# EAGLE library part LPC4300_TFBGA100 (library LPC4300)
TFBGA100 - SOT926-1 TFBGA100: plastic thin fine-pitch ball grid array package; 100 balls body 9 x 9 x 0.7 mm; Solderland 0.40 mm diameter Grid 0.8 x 0.8 mm
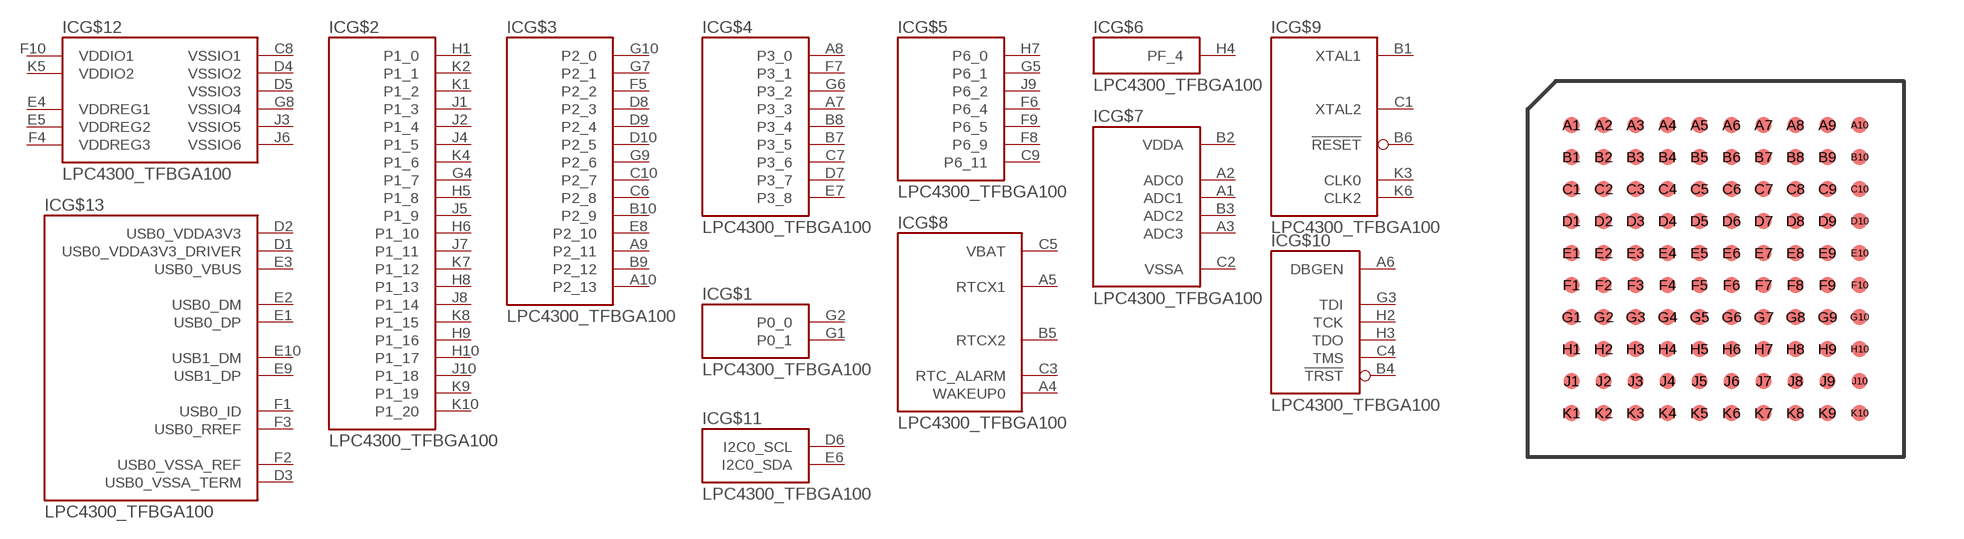
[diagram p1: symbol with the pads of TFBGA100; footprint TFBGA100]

Designator prefix IC; gates G$1=100_1_PORT0 G$2=100_2_PORT1 G$3=100_3_PORT2 G$4=100_4_PORT3 G$5=100_7_PORT6 G$6=100_16_PORTF G$7=100_17_ANA G$8=100_18_RTC G$9=100_19_CLK G$10=100_20_DBUG G$11=100_21_I2C G$12=100_22_SUP G$13=100_23_USB

## LPC4300_TFBGA100  [TFBGA100]
A1  G$7:ADC1  in
A2  G$7:ADC0  in
A3  G$7:ADC3  in
A4  G$8:WAKEUP0  in
A5  G$8:RTCX1  in
A6  G$10:DBGEN  in
A7  G$4:P3_3
A8  G$4:P3_0
A9  G$3:P2_11
A10  G$3:P2_13
B1  G$9:XTAL1  in
B2  G$7:VDDA  sup
B3  G$7:ADC2  in
B4  G$10:!TRST
B5  G$8:RTCX2  out
B6  G$9:!RESET  in
B7  G$4:P3_5
B8  G$4:P3_4
B9  G$3:P2_12
B10  G$3:P2_9
C1  G$9:XTAL2  out
C2  G$7:VSSA  sup
C3  G$8:RTC_ALARM  out
C4  G$10:TMS
C5  G$8:VBAT  pwr
C6  G$3:P2_8
C7  G$4:P3_6
C8  G$12:VSSIO1  sup
C9  G$5:P6_11
C10  G$3:P2_7
D1  G$13:USB0_VDDA3V3_DRIVER
D2  G$13:USB0_VDDA3V3
D3  G$13:USB0_VSSA_TERM
D4  G$12:VSSIO2  sup
D5  G$12:VSSIO3  sup
D6  G$11:I2C0_SCL
D7  G$4:P3_7
D8  G$3:P2_3
D9  G$3:P2_4
D10  G$3:P2_5
E1  G$13:USB0_DP
E2  G$13:USB0_DM
E3  G$13:USB0_VBUS
E4  G$12:VDDREG1  sup
E5  G$12:VDDREG2  sup
E6  G$11:I2C0_SDA
E7  G$4:P3_8
E8  G$3:P2_10
E9  G$13:USB1_DP
E10  G$13:USB1_DM
F1  G$13:USB0_ID
F2  G$13:USB0_VSSA_REF
F3  G$13:USB0_RREF
F4  G$12:VDDREG3  sup
F5  G$3:P2_2
F6  G$5:P6_4
F7  G$4:P3_1
F8  G$5:P6_9
F9  G$5:P6_5
F10  G$12:VDDIO1  sup
G1  G$1:P0_1
G2  G$1:P0_0
G3  G$10:TDI
G4  G$2:P1_7
G5  G$5:P6_1
G6  G$4:P3_2
G7  G$3:P2_1
G8  G$12:VSSIO4  sup
G9  G$3:P2_6
G10  G$3:P2_0
H1  G$2:P1_0
H2  G$10:TCK
H3  G$10:TDO
H4  G$6:PF_4
H5  G$2:P1_8
H6  G$2:P1_10
H7  G$5:P6_0
H8  G$2:P1_13
H9  G$2:P1_16
H10  G$2:P1_17
J1  G$2:P1_3
J2  G$2:P1_4
J3  G$12:VSSIO5  sup
J4  G$2:P1_5
J5  G$2:P1_9
J6  G$12:VSSIO6  sup
J7  G$2:P1_11
J8  G$2:P1_14
J9  G$5:P6_2
J10  G$2:P1_18
K1  G$2:P1_2
K2  G$2:P1_1
K3  G$9:CLK0  out
K4  G$2:P1_6
K5  G$12:VDDIO2  sup
K6  G$9:CLK2  out
K7  G$2:P1_12
K8  G$2:P1_15
K9  G$2:P1_19
K10  G$2:P1_20

## Footprint TFBGA100 (pad centres in mm)
TFBGA100 - SOT926-1 TFBGA100: plastic thin fine-pitch ball grid array package; 100 balls body 9 x 9 x 0.7 mm; Solderland 0.40 mm diameter Grid 0.8 x 0.8 mm
smd 0.4 x 0.4: A1 -3.6,3.6; A2 -2.8,3.6; A3 -2,3.6; A4 -1.2,3.6; A5 -0.4,3.6; A6 0.4,3.6; A7 1.2,3.6; A8 2,3.6; A9 2.8,3.6; A10 3.6,3.6; B1 -3.6,2.8; B2 -2.8,2.8; B3 -2,2.8; B4 -1.2,2.8; B5 -0.4,2.8; B6 0.4,2.8; B7 1.2,2.8; B8 2,2.8; B9 2.8,2.8; B10 3.6,2.8; C1 -3.6,2; C2 -2.8,2; C3 -2,2; C4 -1.2,2; C5 -0.4,2; C6 0.4,2; C7 1.2,2; C8 2,2; C9 2.8,2; C10 3.6,2; D1 -3.6,1.2; D2 -2.8,1.2; D3 -2,1.2; D4 -1.2,1.2; D5 -0.4,1.2; D6 0.4,1.2; D7 1.2,1.2; D8 2,1.2; D9 2.8,1.2; D10 3.6,1.2; E1 -3.6,0.4; E2 -2.8,0.4; E3 -2,0.4; E4 -1.2,0.4; E5 -0.4,0.4; E6 0.4,0.4; E7 1.2,0.4; E8 2,0.4; E9 2.8,0.4; E10 3.6,0.4; F1 -3.6,-0.4; F2 -2.8,-0.4; F3 -2,-0.4; F4 -1.2,-0.4; F5 -0.4,-0.4; F6 0.4,-0.4; F7 1.2,-0.4; F8 2,-0.4; F9 2.8,-0.4; F10 3.6,-0.4; G1 -3.6,-1.2; G2 -2.8,-1.2; G3 -2,-1.2; G4 -1.2,-1.2; G5 -0.4,-1.2; G6 0.4,-1.2; G7 1.2,-1.2; G8 2,-1.2; G9 2.8,-1.2; G10 3.6,-1.2; H1 -3.6,-2; H2 -2.8,-2; H3 -2,-2; H4 -1.2,-2; H5 -0.4,-2; H6 0.4,-2; H7 1.2,-2; H8 2,-2; H9 2.8,-2; H10 3.6,-2; J1 -3.6,-2.8; J2 -2.8,-2.8; J3 -2,-2.8; J4 -1.2,-2.8; J5 -0.4,-2.8; J6 0.4,-2.8; J7 1.2,-2.8; J8 2,-2.8; J9 2.8,-2.8; J10 3.6,-2.8; K1 -3.6,-3.6; K2 -2.8,-3.6; K3 -2,-3.6; K4 -1.2,-3.6; K5 -0.4,-3.6; K6 0.4,-3.6; K7 1.2,-3.6; K8 2,-3.6; K9 2.8,-3.6; K10 3.6,-3.6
